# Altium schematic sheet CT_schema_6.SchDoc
size 143 x 108 mm
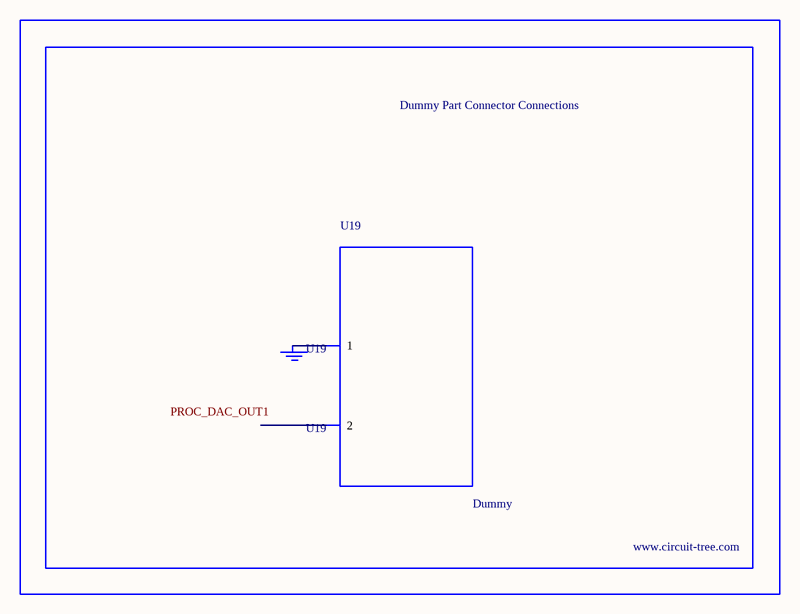
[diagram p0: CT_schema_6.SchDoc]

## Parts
BORDER5  (no value)
GND_INSTANCE_5_0  (no value)
U19  Dummy  [DUMMY_PACKAGE_149]

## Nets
NetGND_INSTANCE_5_0_0: GND_INSTANCE_5_0.0(GND) U19.1

Not connected (* = marked no-connect by the designer): U19 2

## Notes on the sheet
- Labels drawn without touching a wire or pin: PROC_DAC_OUT1

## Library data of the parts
BORDER5 = BORDER_PAGE5
GND_INSTANCE_5_0 = GND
